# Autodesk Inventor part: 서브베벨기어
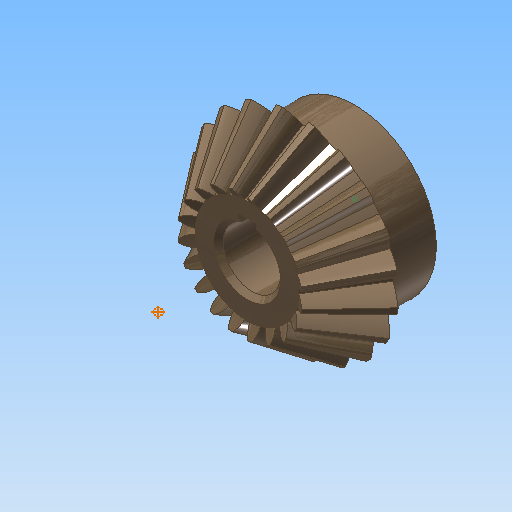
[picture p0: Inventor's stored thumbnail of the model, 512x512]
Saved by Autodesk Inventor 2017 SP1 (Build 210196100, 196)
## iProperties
Created: 2018-09
Part Number: 서브베벨기어
Material: 강철, 탄소
Document SubType Name: Modeling
Categories: <?xml version="1.0" encoding="UTF-16"?> <MemberInstance><Categories><FamilyTemplate><FamilyTemplateParameter ValueType="xs:double" Id="1" ObjectReferenceKey="da
Mass: 135.037 g
Surface Area: 63.6444 cm^2
Volume: 17.1585 cm^3
Density: 7.87 g/cm^3
Appearance: 얼룩무늬
CustomPartVersion: 1
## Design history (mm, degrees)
node "맨 위 점"
node "메쉬 평면2"
sketch "톱니 본체 스케치"
  geometry: L1 (0, 0)-(18.003, -31.331); L2 (18.003, -31.331)-(21.664, -28.891); L3 (21.664, -28.891)-(0, 0); L4 (20, -30)-(0, 0); L5 (10.813, -18.818)-(13.012, -17.352); L6 (18.003, -31.331)-(10.813, -18.818); L7 (21.664, -28.891)-(13.012, -17.352); L8 (0, -39.387)-(0, 6.564) reference; L9 (0, -30)-(21.664, -30)
  constraints: 16 end point, 4 point on line, 3 perpendicular, 2 collinear, 1 horizontal alignment, 1 vertical alignment
  dimensions: "d0" = 40 diameter of L4.start L8 (= da_de); "d1" = 36.00616 diameter of L1.end L8 (= da_dfe); "d2" = 43.3282 diameter of L2.end L8 (= da_dae); "d3" = 14.4 distance between parallel lines of L2 L5 (= da_b); "d4" = 28.8906 vertical distance of L2.end L1.start (= da_ve)
revolve "톱니 본체" sketch "톱니 본체 스케치" stored, may be unused: angle "d5" = 90 deg
node "시작점"
node "톱니 평면"
sketch "시작 스케치"
  geometry: L1 (0, -23.505)-(0, 10.645) reference; L2 (-0.834, -2.928)-(0.834, -2.928); A1 r 8.898 centre (-9.698, -3.713) between (-0.834, -2.928) and (-3.903, 3.04); A2 r 8.898 centre (9.698, -3.713) between (3.903, 3.04) and (0.834, -2.928); A3 r 27.357 centre (0, -24.037) between (3.903, 3.04) and (-3.903, 3.04); 1 further point
  constraints: 6 point on circle, 3 centre point, 3 symmetric about line, 2 end point, 1 coincident, 1 perpendicular, 1 other
  dimensions: "d7" = 8.89846 radius of A1 (= fd_rr); "d8" = 9.69794 horizontal distance of point (0, -24.037) A1.centre (= fd_x); "d9" = 20.32439 vertical distance of point (0, -24.037) A1.centre (= fd_y); "d57" = 27.35701 radius of A3 (= 0.5 x fd_dva + 0.3 x da_he); "d58" = 21.10901 distance from line of A3.centre L2 (= 0.5 x fd_dva - 1.12 x da_he)
node "끝점"
  node "끝 평면"
sketch "3D 스케치 오른쪽"
  node "Helical Curve Right" dims "d65" = 229.90621 (computed from da_dm, da_delta, da_beta), "d66" = 31.5, "d67" = 40 (= da_de), "d68" = -5.88003 (= -da_delta), "d69" = 12.16458 (computed from fd_loft, da_delta)
node "끝 평면 오른쪽"
sketch "끝 스케치 오른쪽"
  geometry: L1 (0, -22.649)-(0, 12.15) reference; L2 (-0.497, -1.72)-(0.497, -1.72); A1 r 5.299 centre (-5.775, -2.187) between (-0.497, -1.72) and (-2.324, 1.834); A2 r 5.299 centre (5.775, -2.187) between (2.324, 1.834) and (0.497, -1.72); A3 r 16.291 centre (0, -14.29) between (2.324, 1.834) and (-2.324, 1.834); 1 further point
  constraints: 6 point on circle, 3 centre point, 3 symmetric about line, 2 end point, 1 coincident, 1 perpendicular, 1 other
  dimensions: "d70" = 5.77526 horizontal distance of A3.centre A1.centre (computed from fd_x, fd_ratio); "d71" = 12.10346 vertical distance of point (0, -14.29) A1.centre (computed from fd_y, fd_ratio); "d72" = 5.29916 radius of A1 (computed from fd_rr, fd_ratio); "d73" = 12.57071 distance from line of point (0, -14.29) L2 (computed from d58, fd_ratio); "d74" = 16.29149 radius of A3 (computed from d57, fd_ratio)
feature "로프트 오른쪽" sketch "끝 스케치 오른쪽" dims "d75" = 0, "d77" = 0, "d79" = 0, "d80" = 90 deg, "d85" = 20, "d92" = 90 deg, "d93" = 90 deg, "da_teethtype" = 0 [user parameter]
sketch "3D 스케치 왼쪽"
  node "Helical Curve Left" dims "d26" = 229.90621 (computed from da_dm, da_delta, da_beta), "d27" = 12.16458 (computed from fd_loft, da_delta), "d28" = 40 (= da_de), "d29" = -5.88003 (= -da_delta)
node "끝 평면 왼쪽"
sketch "끝 스케치 왼쪽" dims "d56" = 10.82768 (derived)
  geometry: L1 (0, -35.087)-(0, 18.089) reference; L2 (-0.497, -1.716)-(0.497, -1.716); A1 r 5.299 centre (-5.775, -2.183) between (-0.497, -1.716) and (-2.324, 1.838); A2 r 5.299 centre (5.775, -2.183) between (2.324, 1.838) and (0.497, -1.716); A3 r 16.291 centre (0, -14.287) between (2.324, 1.838) and (-2.324, 1.838); 2 further points; 1 other entity
  constraints: 6 point on circle, 3 centre point, 3 symmetric about line, 2 end point, 1 coincident, 2 other
  dimensions: "d30" = 5.29916 radius of A1 (computed from fd_rr, fd_ratio); "d31" = 5.77526 horizontal distance of point (0, -14.287) A1.centre (computed from fd_x, fd_ratio); "d32" = 12.10346 vertical distance of A1.centre point (0, -14.287) (computed from fd_y, fd_ratio); "d61" = 16.29149 radius of A3 (computed from d57, fd_ratio); "d62" = 12.57071 distance from line of point (0, -14.287) L2 (computed from d58, fd_ratio)
feature "로프트 왼쪽" sketch "끝 스케치 왼쪽" dims "d35" = 0, "d37" = 0, "d39" = 0, "d40" = 90 deg, "d84" = 10, "d90" = 90 deg, "d91" = 90 deg, "da_teethtype" = 0 [user parameter]
sketch "본체 스케치"
  geometry: L1 (0, -35.038)-(0, -19.531) reference; L2 (18.003, -31.331)-(10.813, -18.818) reference; L3 (10.813, -18.818)-(0, -18.818); L4 (18.003, -31.331)-(0, -31.331)
  constraints: 4 end point, 2 perpendicular, 2 point on line
revolve "본체 고정" sketch "본체 스케치" stored, may be unused: angle "d46" = 90 deg
feature "피치 지름" dims angle "d47" = 90 deg
sketch "스케치8"
  geometry: C1 r 17 at (0, 0); 1 further point
  constraints: 1 centre point, 1 coincident
  dimensions: "d94" = 34 diameter of C1
extrude "돌출1" join sketch "스케치8" distance "d95" = 10; taper "d96" = 0 deg
sketch "스케치9"
  geometry: 1 further point
hole "구멍1" sketch "스케치9" at (0, 0) diameter "d97" = 12; stored, may be unused: countersink angle "d101" = 90 deg, drill point angle "d103" = 118 deg; dims "d98" = 6, "d99" = 4, "d100" = 2, "d102" = 8
sketch "스케치10"
  geometry: 1 further point
sketch "스케치11"
  geometry: 1 further point
sketch "스케치12"
  geometry: L1 (-2, 5.657)-(-2, 7.8); L2 (-2, 7.8)-(2, 7.8); L3 (2, 7.8)-(2, 5.657); A1 r 6 centre (0, 0) between (-2, 5.657) and (2, 5.657) reference; 1 further point
  constraints: 6 end point, 2 parallel, 2 point on circle, 1 perpendicular, 1 vertical
  dimensions: "d104" = 4 distance of L1.end L2.end; "d105" = 13.8 dimension on A1 L2
extrude "돌출2" cut sketch "스케치12" stored distance "d106" = 7; taper "d107" = 0 deg
chamfer "모따기1" distance "d108" = 1; stored, may be unused: second distance "d109" = 2, angle "d110" = 45 deg
body "Solid1"
feature "로프트" dims "d17" = 0, "d18" = 90 deg, "d19" = 0, "d20" = 90 deg, "d89" = 0, "da_teethtype" = 0 [user parameter]
pattern_circular "원형 패턴" dims angle "d22" = 360 deg, "d88" = 0, "da_teethtype" = 0 [user parameter]
pattern_circular "원형 패턴 오른쪽" dims angle "d82" = 360 deg, "da_teethtype" = 0 [user parameter]
pattern_circular "원형 패턴 왼쪽" dims angle "d42" = 360 deg, "da_teethtype" = 0 [user parameter]
sketch "끝 스케치"
  geometry: L1 (0, -15.359)-(0, 6.983) reference; L2 (-0.497, -1.72)-(0.497, -1.72); A1 r 5.299 centre (-5.775, -2.187) between (-0.497, -1.72) and (-2.324, 1.834); A2 r 5.299 centre (5.775, -2.187) between (2.324, 1.834) and (0.497, -1.72); A3 r 16.291 centre (0, -14.29) between (2.324, 1.834) and (-2.324, 1.834); 1 further point
  constraints: 6 point on circle, 3 centre point, 3 symmetric about line, 2 end point, 1 coincident, 1 other
  dimensions: "d12" = 5.29916 radius of A1 (computed from fd_rr, fd_ratio); "d15" = 5.77526 horizontal distance of A1.centre point (0, -14.29) (computed from fd_x, fd_ratio); "d16" = 12.10346 vertical distance of A1.centre point (0, -14.29) (computed from fd_y, fd_ratio); "d59" = 16.29149 radius of A3 (computed from d57, fd_ratio); "d60" = 12.57071 distance from line of A3.centre L2 (computed from d58, fd_ratio)
sketch "Sketch6"
  geometry: L1 (20, -30)-(0, 0) reference; L2 (0, -37.8)-(0, 6.3) reference
body "Srf1"
other parameters: "da_b" = 14.4 [user parameter; used in 2 equation terms], "da_de" = 40 [user parameter; used in 4 equation terms], "da_dae" = 43.3282 [user parameter; used in 2 equation terms], "da_dfe" = 36.00616 [user parameter; used in 1 equation term], "da_le" = 36.05551 [user parameter; used in 1 equation term], "da_omega" = 90 deg [user parameter; used in 1 equation term], "da_beta" = 0 [user parameter; used in 2 equation terms], "da_delta" = 5.88003 [user parameter; used in 8 equation terms], "da_alpha" = 20 deg [user parameter; used in 2 equation terms], "da_he" = 4.4 [user parameter; used in 4 equation terms], "da_ve" = 28.8906 [user parameter; used in 1 equation term], "fd_dv" = 48.07402 (computed from da_de, da_delta) [user parameter; used in 1 equation term], "fd_dva" = 52.07402 (computed from da_dae, da_delta) [user parameter; used in 3 equation terms], "fd_dvb" = 45.1748 (computed from fd_dv, da_alpha) [user parameter; used in 2 equation terms], "da_zv" = 240.37008 [user parameter; used in 1 equation term], "fd_loft" = 14.62 (= da_b + 0.05 x da_he) [user parameter; used in 4 equation terms], "fd_ratio" = 5.95514 (computed from da_le, fd_loft) [user parameter; used in 15 equation terms], "fd_rr" = 8.89846 (computed from fd_dd, fd_dvb) [user parameter; used in 6 equation terms], "fd_angle" = 0.66075 (computed from da_zv) [user parameter; used in 4 equation terms], "fd_x1" = 1.58709 (computed from da_dvw, fd_angle) [user parameter; used in 1 equation term], "fd_y1" = 23.98456 (computed from da_dvw, fd_angle) [user parameter; used in 1 equation term], "fd_x2" = 8.11084 (computed from fd_rr, fd_angle2, fd_angle) [user parameter; used in 1 equation term], "fd_y2" = 3.66016 (computed from fd_rr, fd_angle2, fd_angle) [user parameter; used in 1 equation term], "fd_x" = 9.69794 (= fd_x1 + fd_x2) [user parameter; used in 4 equation terms], "fd_y" = 20.32439 (= fd_y1 - fd_y2) [user parameter; used in 4 equation terms], "fd_angle2" = 3.57832 (computed from fd_dvb, fd_dd, da_alpha) [user parameter; used in 2 equation terms], "fd_dd" = 48.55402 (= fd_dva - 0.8 x da_he) [user parameter; used in 2 equation terms], "da_dvw" = 48.07402 [user parameter; used in 2 equation terms], "d11" = 14.62 (= fd_loft), "da_dm" = 32.01232 [user parameter; used in 2 equation terms], "da_x" = 0 [user parameter], "da_m" = 2 [user parameter], "d48" = 0, "d49" = 0, "d50" = 90 deg (= da_omega), "d51" = 9 deg (computed from da_z), "d52" = 0, "d53" = 0, "d54" = 0
